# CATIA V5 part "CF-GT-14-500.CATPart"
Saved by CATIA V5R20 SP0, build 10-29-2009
Part number: CF-GT-14-500
Definition: NONE
Nomenclature: CF-GT-14-500
Source: Unknown
Description: CF-GT-14-500
Bounding box of the stored display mesh (mm): x 0 to 500, y 0 to 24, z -12 to 12
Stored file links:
  C:\Users\Utente\Desktop\IO LAVORO\3D X SITO CF\X SITO\PLASTICA\CF-GT\CF-GT-14-500.CATPart
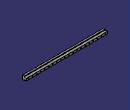
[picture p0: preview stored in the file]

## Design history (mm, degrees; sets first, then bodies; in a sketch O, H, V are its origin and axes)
Body1 "CF-GT-14-500" (main body)
  Solid1: solid without history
